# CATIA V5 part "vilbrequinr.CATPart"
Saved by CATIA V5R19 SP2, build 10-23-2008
Part number: vilbrequinr
Bounding box of the stored display mesh (mm): x -34.901 to 34.901, y 0 to 370, z -89.552 to 89.552
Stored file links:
  C:\Users\marc\Desktop\boulot\Semestre 3\CFAO\Projet CFAO\robuste\vilbrequinr.CATPart
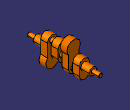
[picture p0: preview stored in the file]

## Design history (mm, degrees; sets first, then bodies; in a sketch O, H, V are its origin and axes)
Parameters
  rayvilext = 10 mm
  longextr = 40 mm
  rayvilfix = 20 mm
  longfix = 45 mm
  hautgdbr = 66 mm
  demilargvil = 26 mm
  raytete = 15 mm
  raycerlequili = 35 mm
  longequi = 35 mm
  largbielle = 20 mm
  LENGTH = 0 mm
  LENGTH = 0 mm
Body1 (main body)
  Sketch1 on zx-plane, origin (0, 0, 0), H (-1, 0, 0), V (0, 0, 1)
    circle A1 centre (0, 0) radius 10
    radius A1 = 10 {= rayvilext}
  Pad1: profile Sketch1, direction (0, 1, 0), length 40 {= longextr}
  Sketch2 on end face of Pad1, origin (0, 40, 0), H (-1, 0, 0), V (0, 0, 1)
    circle A1 centre (0, 0) radius 20
    reference projected circle E1 centre (0, 0) radius 10 from edge [face of Pad1 from Sketch1.A1 | end face of Pad1]
    radius A1 = 20 {= rayvilfix}
    concentricity: A1 E1
  Pad2: profile Sketch2, direction (0, 1, 0), length 45 {= longfix}
  Chamfer1: length 2, angle 45, on edge [start face of Pad1 | face of Pad1 from Sketch1.A1]
  Sketch3 on end face of Pad2, origin (0, 85, 0), H (-1, 0, 0), V (0, 0, 1)
    line L1 (-26, 33) -> (-26, -33)
    point P1 (-26, 33)
    line L2 (26, 33) -> (26, -33)
    point P3 (26, 33)
    point P5 (0, 110)
    arc A1 centre (0, 33) radius 26 from (-26, 33) to (26, 33) cw
    point P7 (0, 59)
    arc A2 centre (0, -56.4307) radius 35 from (-26, -33) to (26, -33) ccw
    distance V L1 = 26 {= demilargvil}
    distance V L2 = 26 {= demilargvil}
    length L2 = 66 {= hautgdbr}
    length L1 = 66 {= hautgdbr}
    distance H P3 = 33 {= hautgdbr /2}
    distance H P1 = 33 {= hautgdbr /2}
    radius A1 = 26 {= demilargvil}
    radius A2 = 35 {= raycerlequili}
    vertical: L1 V, L2 V
    coincidence: P5 V, A1 P7, P7 V
  Pad3: profile Sketch3, direction (0, 1, 0), length 35 {= longequi}
  Sketch4 on end face of Pad3, origin (0, 120, 0), H (-1, 0, 0), V (0, 0, 1)
    circle A1 centre (0, 33) radius 15
    point P1 (0, 33)
    radius A1 = 15 {= raytete}
    distance O P1 = 33 {= hautgdbr /2}
    coincidence: P1 V
  Pad4: profile Sketch4, direction (0, 1, 0), length 20 {= largbielle}
  Sketch5 on end face of Pad4, origin (0, 140, 0), H (-1, 0, 0), V (0, 0, 1)
    line L1 (26, 33) -> (26, -11)
    point P1 (26, 33)
    line L2 (-26, 33) -> (-26, -11)
    point P3 (-26, 33)
    arc A1 centre (0, 33) radius 26 from (-26, 33) to (26, 33) cw
    arc A2 centre (0, -11) radius 26 from (-26, -11) to (26, -11) ccw
    length L2 = 44 {= hautgdbr/1.5}
    length L1 = 44 {= hautgdbr/1.5}
    distance H P1 = 33 {= hautgdbr /2}
    distance P3 H = 33 {= hautgdbr /2}
    distance V L1 = 26 {= demilargvil}
    distance V L2 = 26 {= demilargvil}
    radius A1 = 26 {= demilargvil}
    vertical: L1 V, L2 V
    tangency: A2 L2
  Pad5: profile Sketch5, direction (0, 1, 0), length 35 {= longequi}
  Sketch6 on end face of Pad5, origin (0, 175, 0), H (-1, 0, 0), V (0, 0, 1)
    circle A1 centre (0, 0) radius 20
    point P1 (20, 0)
    reference projected circle E1 centre (0, 0) radius 20 from edge [start face of Pad2 | face of Pad2 from Sketch2.A1]
    radius A1 = 20 {= rayvilfix}
    coincidence: A1 P1, P1 H
    concentricity: A1 E1
  Pad6: profile Sketch6, direction (0, 1, 0), length 20 {= largbielle}
  Sketch7 on end face of Pad6, origin (0, 195, 0), H (-1, 0, 0), V (0, 0, 1)
    line L1 (26, 33) -> (26, -33)
    point P1 (26, 33)
    line L2 (-26, -33) -> (-26, 33)
    point P4 (-26, 33)
    arc A1 centre (0, 56.4307) radius 35 from (-26, 33) to (26, 33) cw
    arc A2 centre (0, -33) radius 26 from (-26, -33) to (26, -33) ccw
    length L2 = 66 {= hautgdbr}
    length L1 = 66 {= hautgdbr}
    distance V L1 = 26 {= demilargvil}
    distance V L2 = 26 {= demilargvil}
    distance P1 H = 33 {= hautgdbr /2}
    distance H P4 = 33 {= hautgdbr /2}
    radius A1 = 35 {= raycerlequili}
    vertical: L1 V, L2 V
    tangency: A2 L1
  Pad7: profile Sketch7, direction (0, 1, 0), length 35 {= longequi}
  Sketch8 on end face of Pad7, origin (0, 230, 0), H (-1, 0, 0), V (0, 0, 1)
    circle A1 centre (0, -33) radius 15
    point P1 (0, -33)
    radius A1 = 15 {= raytete}
    distance O P1 = 33 {= hautgdbr /2}
  Pad8: profile Sketch8, direction (0, 1, 0), length 20 {= largbielle}
  Sketch9 on end face of Pad8, origin (0, 250, 0), H (-1, 0, 0), V (0, 0, 1)
    line L1 (26, 11) -> (26, -33)
    line L2 (-26, 11) -> (-26, -33)
    arc A1 centre (0, 11) radius 26 from (-26, 11) to (26, 11) cw
    arc A2 centre (0, -33) radius 26 from (-26, -33) to (26, -33) ccw
    reference projected circle E1 centre (0, -33) radius 15 from edge [face of Pad8 from Sketch8.A1 | end face of Pad8]
    length L2 = 44 {= hautgdbr/1.5}
    length L1 = 44 {= hautgdbr/1.5}
    distance V L1 = 26 {= demilargvil}
    distance V L2 = 26 {= demilargvil}
    radius A1 = 26 {= demilargvil}
    vertical: L1 V, L2 V
    tangency: A2 L2
    concentricity: A2 E1
  Pad9: profile Sketch9, direction (0, 1, 0), length 35 {= longequi}
  Sketch10 on end face of Pad9, origin (0, 285, 0), H (-1, 0, 0), V (0, 0, 1)
    circle A1 centre (0, 0) radius 20
    reference projected circle E1 centre (0, 0) radius 20 from edge [start face of Pad2 | face of Pad2 from Sketch2.A1]
    radius A1 = 20 {= rayvilfix}
    concentricity: A1 E1
  Pad10: profile Sketch10, direction (0, 1, 0), length 45 {= longfix}
  Sketch11 on end face of Pad10, origin (0, 330, 0), H (-1, 0, 0), V (0, 0, 1)
    circle A1 centre (0, 0) radius 10
    radius A1 = 10 {= rayvilext}
  Pad11: profile Sketch11, direction (0, 1, 0), length 40 {= longextr}
  Chamfer2: length 2, angle 45, on edge [face of Pad11 from Sketch11.A1 | end face of Pad11]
